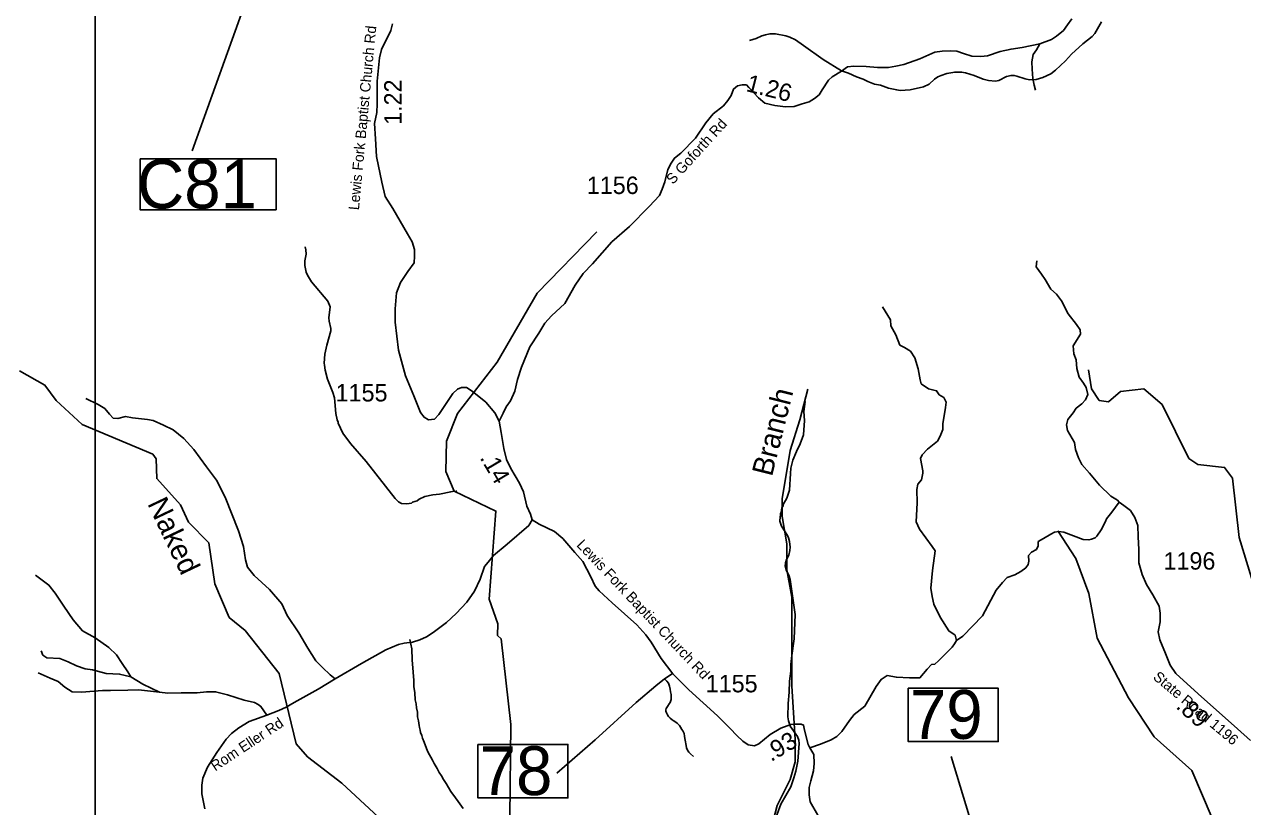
# Model space of a CAD drawing. Extents: x 1248089 to 1457196, y 820910 to 988753.
# Drawn here: x 1300259 to 1308985, y 877278 to 882884 of the extents above; entities that cross this region are included whole.
import ezdxf

# ---------------------------------------------------------------- set-up
doc = ezdxf.new("R2010")
doc.units = 0
for name, color, linetype in [('Exist Hydrographic Creek Single Shore', 7, 'Continuous'), ('Exist Hydrographic Misc Water Feature', 7, 'Continuous'), ('Exist Road Non-System Type 51', 7, 'Continuous'), ('Exist Road Secondary Structure Standard Bridge Number Label', 7, 'Continuous'), ('Exist Road Secondary Type 51 Attributed', 7, 'Continuous'), ('Exist Road Secondary Type 51 Label', 7, 'Continuous'), ('Map Preparation Inset Cut Line', 7, 'Continuous'), ('Prop GRAU CAT1 Cell', 7, 'Continuous'), ('Prop Guardrail Anchor Unit CELL', 7, 'Continuous'), ('Prop Lane Lines', 7, 'Continuous')]:
    doc.layers.add(name, color=color, linetype=linetype)

msp = doc.modelspace()

# ---------------------------------------------------------------- linework, layer by layer
at = {"layer": 'Exist Hydrographic Creek Single Shore'}
for points in [[(1304309.1, 876054.1), (1304084.2, 876058.7), (1303941.2, 875963), (1303891.1, 875980.4), (1303482.2, 876330.1), (1303255.2, 876594), (1302957.1, 877053), (1302532, 877445.5), (1302287.1, 877634.4), (1302205.1, 877727.9), (1302084.1, 878232.5), (1301841, 878539.5), (1301726.1, 878633.7), (1301624.1, 878875.4), (1301580, 879168.5), (1301434, 879315.8), (1301378, 879441.7), (1301207, 879628.9), (1301202, 879770.2), (1301178, 879803.5), (1300674, 880017.2), (1300487, 880188.3), (1300406, 880298.3), (1300225, 880400.4)], [(1304607.2, 875923.4), (1304830.5, 876199), (1305073.4, 876522.9), (1305142.8, 876580.8), (1305200.7, 876708), (1305362.6, 876835.2), (1305593.9, 877066.6), (1305651.8, 877286.4), (1305744.3, 877471.4), (1305779, 877598.7), (1305779, 877760.6), (1305755.9, 878142.3), (1305755.9, 878558.8), (1305755.9, 878778.5), (1305721.2, 878975.2), (1305721.2, 879160.2), (1305686.5, 879356.9), (1305686.5, 879484.1), (1305744.3, 879831.1), (1305813.7, 880050.9), (1305871.6, 880270.7)], [(1309746.2, 875554.1), (1309743.2, 875561), (1309715.2, 875778.2), (1309626.2, 875914.6), (1309588.3, 876046.7), (1309463.2, 876075.5), (1309365.2, 876136.5), (1309301.2, 876272.4), (1309271.3, 876414.1), (1309167.2, 876606.7), (1308835.2, 877033.5), (1308622.2, 877536.8), (1308352.2, 877778.6), (1308167.2, 878058), (1307943.2, 878486), (1307884.2, 878805.7), (1307790.2, 879057.1), (1307661.1, 879253.3)]]:
    msp.add_lwpolyline(points, dxfattribs=at)
at = {"layer": 'Exist Hydrographic Misc Water Feature'}
for points in [[(1305453.4, 882767.9), (1305501.7, 882782.5), (1305542.3, 882801.4), (1305566.5, 882808.6), (1305598.7, 882815.7), (1305638.8, 882816.5), (1305712.4, 882802.5), (1305742.2, 882791.6), (1305783.6, 882772.5), (1305839.8, 882731.8), (1305981.8, 882632.7), (1306111.5, 882551), (1306161.1, 882533.6), (1306218.3, 882507.9), (1306267.9, 882490.5), (1306301.4, 882473.5), (1306348.9, 882456.2), (1306390.7, 882446.9), (1306448.2, 882425.3), (1306507.8, 882413.6), (1306531.7, 882410.8), (1306603.9, 882414.8), (1306700.5, 882436), (1306739, 882454.9), (1306778.1, 882491.7), (1306802.6, 882507), (1306826.9, 882518.3), (1306867.3, 882531.1), (1306923.6, 882541.6), (1306971.7, 882542.2), (1306999.4, 882537.4), (1307063, 882517.5), (1307126.3, 882491.6), (1307166, 882482.5), (1307213.9, 882477.2), (1307238, 882480.5), (1307294.8, 882508.8), (1307327.1, 882517.9), (1307349.1, 882517.3), (1307368.9, 882512.7), (1307426.5, 882493), (1307458.2, 882486.1), (1307506.3, 882488.7), (1307554.7, 882503.3), (1307611.5, 882529.7), (1307644.2, 882554.7), (1307716.2, 882622.6), (1307759.6, 882669.3), (1307841.7, 882744.9), (1307907.2, 882797.1), (1307925.8, 882818.5), (1307974.2, 882901)], [(1304309.1, 876054.1), (1304307.2, 876297.2), (1304236.1, 876482.4), (1303767.1, 877109), (1303736.1, 877201.5), (1303743.1, 877867.7), (1303674.1, 878479.7), (1303649.1, 878503.2), (1303651.1, 878588.5), (1303589.1, 878763.8), (1303637.1, 879396.4), (1303337.6, 879538.2), (1303277.1, 879679.4), (1303282, 879895.9), (1303361.1, 880094.6), (1303645.1, 880463.1), (1303932, 880956.4), (1304359.1, 881397.5)], [(1302270.4, 881288.4), (1302275.9, 881268.3), (1302277, 881236.3), (1302267.7, 881188.5), (1302266.7, 881156.5), (1302277.4, 881108.3), (1302286.7, 881086), (1302315.4, 881039.3), (1302431.6, 880899.9), (1302448.4, 880859.4), (1302440.2, 880779.7), (1302441.5, 880755.7), (1302454.1, 880703.3), (1302453.6, 880687.4), (1302424.7, 880584.2), (1302410.9, 880520.6), (1302407.1, 880456.7), (1302408.6, 880440.7), (1302413.7, 880406.6), (1302429.9, 880342.2), (1302469.1, 880245), (1302480.1, 880206.7), (1302491, 880094.5), (1302499.7, 880050.2), (1302507.3, 880034), (1302507.1, 880026), (1302541, 879953.1), (1302594.9, 879879.5), (1302707.4, 879752.3), (1302914, 879486.4), (1302939.3, 879461.7), (1302959.1, 879451.1), (1302999, 879447.9), (1303031.2, 879453.1), (1303039.3, 879458.8), (1303071.7, 879469.9), (1303088, 879481.4), (1303128.5, 879500.2), (1303184.9, 879512.5), (1303233, 879517.2), (1303313.5, 879534.9), (1303337.6, 879538.2), (1303349.6, 879535.8), (1303357.7, 879541.6)], [(1309100.2, 878745.1), (1308961.1, 879207.5), (1308912.1, 879632), (1308856.2, 879708.6), (1308664.1, 879728.9), (1308599.1, 879772.9), (1308408.1, 880160.8), (1308277.2, 880271.8), (1308110.2, 880252.1), (1308025.2, 880178.3), (1307958.1, 880189.5), (1307902.2, 880272.7), (1307880.1, 880407.7)], [(1305850.7, 880181.3), (1305842.7, 880109.5), (1305846.9, 880045.5), (1305840.1, 879941.7), (1305816.3, 879878.4), (1305788.7, 879823.2), (1305762.9, 879759.9), (1305749.3, 879704.4), (1305745.8, 879664.4), (1305738.9, 879544.7), (1305719.3, 879489.4), (1305694, 879442.1), (1305693.7, 879434.1), (1305685.3, 879418.3), (1305680.3, 879386.4), (1305676.1, 879378.6), (1305675.7, 879362.6), (1305671.5, 879354.8), (1305670.6, 879322.8), (1305681.6, 879288.5), (1305725.8, 879221.3), (1305733.2, 879205), (1305740.5, 879176.8), (1305745.3, 879136.7), (1305742.7, 879112.8), (1305733.8, 879081), (1305716.9, 879049.5), (1305710.3, 879025.7), (1305709.6, 879001.8), (1305716.7, 878971.6), (1305735.8, 878937.1), (1305744.8, 878904.8), (1305779.9, 878655.8), (1305772.9, 878480.1), (1305755.6, 878360.7), (1305749.8, 878296.8), (1305748.4, 878248.9), (1305740.4, 878177.1), (1305738.2, 878097.3), (1305729.9, 878017.5), (1305727.2, 877921.6), (1305732.4, 877893.4), (1305745.3, 877855.1), (1305797.2, 877779.6), (1305806.6, 877755.3), (1305807.9, 877731.4), (1305798.4, 877603.6), (1305784.3, 877532), (1305771, 877484.5), (1305749.1, 877421.1), (1305677.6, 877295.2), (1305625.6, 877152.8)]]:
    msp.add_lwpolyline(points, dxfattribs=at)
at = {"layer": 'Exist Road Non-System Type 51'}
msp.add_line((1304898.5, 878229.8), (1304843.5, 878193.1), dxfattribs=at)
for points in [[(1307531.8, 882743.2), (1307507.8, 882701.1), (1307486, 882667.1), (1307476.3, 882616.1), (1307478.7, 882562.7), (1307483.5, 882494.7), (1307493.2, 882448.5), (1307500.5, 882412.1)], [(1307732.2, 880053.2), (1307770.8, 880099.6), (1307793.4, 880132.8), (1307833.5, 880164.2), (1307859.7, 880193.8), (1307875.3, 880232.2), (1307864.8, 880280.3), (1307845.7, 880313.5), (1307814.3, 880355.3), (1307796.9, 880418.1), (1307793.4, 880480.9), (1307776, 880522.8), (1307770.7, 880580.3), (1307824.8, 880664), (1307821.2, 880694.1), (1307795, 880732.4), (1307735.8, 880809.2), (1307688.7, 880903.4), (1307652.1, 880950.5), (1307610.3, 880987.1), (1307571.9, 881055.1), (1307544.1, 881093.5), (1307505.7, 881145.8), (1307510.9, 881189.4)], [(1306936.9, 878468.2), (1306925.2, 878506.1), (1306882, 878537.5), (1306819.3, 878635.6), (1306772.2, 878729.8), (1306760.5, 878784.7), (1306752.6, 878843.6), (1306764.4, 878969.2), (1306784, 879110.5), (1306760.5, 879141.9), (1306670.3, 879267.4), (1306646.7, 879318.5), (1306654.6, 879455.8), (1306650.7, 879550), (1306658.5, 879589.2), (1306685.9, 879620.6), (1306693.8, 879667.7), (1306693.8, 879683.4), (1306678.1, 879773.7), (1306689.8, 879799.4), (1306729, 879838.6), (1306799.6, 879897.5), (1306819.2, 879932.8), (1306838.8, 879979.9), (1306838.8, 880023.1), (1306846.6, 880078), (1306855.8, 880138.2), (1306861, 880177.5), (1306845.3, 880208.8), (1306811.3, 880229.8), (1306793, 880258.6), (1306735.5, 880271.6), (1306683.2, 880308.3), (1306675.4, 880337), (1306662.3, 880415.5), (1306636.2, 880494), (1306607.4, 880541.1), (1306563, 880567.3), (1306529, 880585.6), (1306500.2, 880658.9), (1306466.2, 880724.3), (1306463.6, 880766.1), (1306406.1, 880860.3)], [(1300698.6, 880202.1), (1300788.4, 880160.8), (1300834.6, 880131.7), (1300868.5, 880090.4), (1300895.2, 880061.2), (1300929.2, 880058.8), (1300982.6, 880073.4), (1301033.6, 880063.7), (1301140.4, 880051.5), (1301181.6, 880044.2), (1301254.4, 880012.7), (1301324.8, 879978.6), (1301400.1, 879915.5), (1301472.9, 879837.8), (1301562.7, 879713.9), (1301635.5, 879616.8), (1301696.1, 879495.3), (1301793.2, 879254.9), (1301829.6, 879143.1), (1301843.5, 879045.7), (1301858, 878994.7), (1301904.1, 878933.9), (1302015.8, 878834.4), (1302103.2, 878732.4), (1302142, 878647.3), (1302224.5, 878523.5), (1302290, 878414.2), (1302345.9, 878321.9), (1302394.4, 878275.7), (1302450.2, 878222.3), (1302484.2, 878193.2)], [(1308100.2, 879460), (1308047.9, 879388.5), (1308011.3, 879341.4), (1308002.6, 879320.4), (1307973, 879261.1), (1307939.9, 879215.8), (1307929.4, 879205.3), (1307903.3, 879194.8), (1307884.1, 879189.6), (1307844, 879191.4), (1307774.3, 879217.5), (1307704.6, 879245.4), (1307668, 879248.9), (1307636.6, 879243.7), (1307612.2, 879231.5), (1307558.2, 879200.1), (1307521.6, 879177.4), (1307519.8, 879147.8), (1307509.4, 879121.6), (1307472.8, 879102.4), (1307451.8, 879078), (1307453.6, 879036.1), (1307448.4, 879013.4), (1307432.7, 878989)], [(1300339.7, 878936.4), (1300434.4, 878866), (1300480.5, 878807.7), (1300541.2, 878715.4), (1300609.1, 878615.8), (1300674.7, 878538.1), (1300766.9, 878487.1), (1300864, 878419.1), (1300919.8, 878365.6), (1300958.6, 878304.9), (1300999.9, 878244.2), (1301021.7, 878207.8), (1301106.7, 878156.8), (1301228, 878098.5), (1301286.3, 878091.2), (1301380.9, 878093.6), (1301497.4, 878093.6), (1301563, 878100.9), (1301628.5, 878100.9), (1301713.4, 878079.1), (1301832.4, 878040.2), (1301907.6, 878023.2), (1301934.3, 878011), (1301953.7, 877996.5), (1301995.1, 877933.8)], [(1305884.7, 877700.5), (1305960.4, 877726.5), (1306038.8, 877757.9), (1306078, 877781.4), (1306113.3, 877816.7), (1306168.2, 877895.2), (1306203.5, 877938.4), (1306278, 877997.3), (1306360.4, 878138.5), (1306395.7, 878189.6), (1306438.8, 878217), (1306505.5, 878205.3), (1306599.6, 878201.3), (1306674.1, 878201.3), (1306725.1, 878264.1), (1306756.5, 878295.5), (1306780, 878299.4), (1306807.5, 878323), (1306905.5, 878421.1), (1306921.2, 878444.6), (1306936.9, 878468.2), (1306980, 878499.6), (1307121.2, 878644.8), (1307219.2, 878829.2), (1307266.3, 878884.2), (1307297.7, 878919.5), (1307352.6, 878939.1), (1307395.7, 878962.7), (1307432.7, 878989)], [(1303020.8, 878475.8), (1303033.3, 878409.3), (1303037.5, 878329.2), (1303043.6, 878241), (1303048.2, 878182.9), (1303049.1, 878138.9), (1303056, 878092.7), (1303058.8, 878042.6), (1303064.2, 878014.5), (1303067.7, 877986.4), (1303074.9, 877956.2), (1303076, 877922.2), (1303081.4, 877891.9), (1303086.5, 877859.7), (1303088.3, 877845.7), (1303093.9, 877825.6), (1303097.5, 877809.5), (1303104.9, 877787.3), (1303110.5, 877769.2), (1303122, 877739), (1303131.2, 877712.7), (1303144.6, 877682.3), (1303152.1, 877666.1), (1303161.8, 877649.9), (1303169.5, 877633.7), (1303183, 877611.4), (1303194.4, 877587.2), (1303215.6, 877550.6), (1303230.9, 877522.2), (1303246.4, 877499.9), (1303261.7, 877471.4), (1303281.2, 877445), (1303313.8, 877386.3), (1303346.7, 877341.4), (1303366.2, 877315), (1303401, 877264.1)], [(1301021.7, 878207.8), (1300941.5, 878228.2), (1300844.4, 878233.1), (1300747.4, 878257.4), (1300694, 878264.7), (1300633.3, 878286.5), (1300572.6, 878315.7), (1300511.9, 878340), (1300419.7, 878344.8), (1300390.6, 878364.2), (1300378.5, 878393.4)], [(1301228, 878098.5), (1301077.4, 878114.1), (1300999.8, 878111.6), (1300876, 878109.2), (1300817.7, 878109.2), (1300667.3, 878099.5), (1300601.7, 878101.9), (1300548.3, 878133.5), (1300499.8, 878174.8), (1300444, 878199.1), (1300356.6, 878237.9)], [(1304073.4, 877517), (1304347.9, 877756.4), (1304642, 878023.3), (1304783.2, 878144.9), (1304843.5, 878193.1)], [(1304843.5, 878193.1), (1304861.2, 878176.7), (1304872.9, 878162.5), (1304880.5, 878140.3), (1304883.9, 878120.2), (1304887.5, 878100.1), (1304891.1, 878081.9), (1304892.6, 878067.8), (1304892.2, 878045.8), (1304883.8, 878024.2), (1304877.6, 878014.3), (1304865, 877996.5), (1304856.7, 877980.7), (1304854.5, 877972.7), (1304854.3, 877962.7), (1304858.1, 877950.6), (1304865.6, 877936.5), (1304873.4, 877924.3), (1304885.1, 877911.9), (1304898.9, 877899.6), (1304906.8, 877895.4), (1304918.7, 877889.2), (1304934.2, 877876.9), (1304946, 877864.4), (1304951.9, 877858.3), (1304959.7, 877848.1), (1304969.4, 877831.9), (1304975.2, 877821.8), (1304984.6, 877801.6), (1304988.2, 877783.5), (1304989.8, 877765.5), (1304995.2, 877741.4), (1304996.9, 877727.3), (1304998.7, 877717.3), (1305002.3, 877699.2), (1305007.8, 877682.9), (1305017.5, 877668.7), (1305029.3, 877656.4), (1305050.9, 877638)]]:
    msp.add_lwpolyline(points, dxfattribs=at)
at = {"layer": 'Exist Road Secondary Structure Standard Bridge Number Label'}
msp.add_line((1307919.3, 874272), (1306898.1, 877637.1), dxfattribs=at)
for points in [[(1306590.1, 878126.4), (1307234.2, 878126.4), (1307234.2, 877744.1), (1306590.1, 877744.1)], [(1303508, 877723.4), (1304152.2, 877723.4), (1304152.2, 877341.1), (1303508, 877341.1)]]:
    msp.add_lwpolyline(points, close=True, dxfattribs=at)
at = {"layer": 'Exist Road Secondary Type 51 Attributed'}
for points in [[(1302896, 882887.6), (1302882.8, 882839.6), (1302816.7, 882702.3), (1302803.4, 882644.4), (1302785.3, 882477.4), (1302787.1, 882404.1), (1302787.1, 882313.2), (1302783.8, 882251.9), (1302767.2, 882174.2), (1302773.8, 882063.4), (1302782.1, 881936), (1302818.3, 881753.3), (1302843.1, 881650.8), (1302897.7, 881563.1), (1303003.5, 881382.8), (1303036.3, 881324.2), (1303052.9, 881269.6), (1303054.5, 881221.6), (1303051.2, 881175.3), (1303006.6, 881112.4), (1302952, 881033), (1302925.6, 880960.2), (1302915.7, 880844.4), (1302914.2, 880749.5), (1302939, 880549.3), (1302988.5, 880364.1), (1303047.9, 880220.9), (1303097.5, 880101.8), (1303122.3, 880068.7), (1303153.7, 880048.8), (1303196.6, 880055.4), (1303228, 880086.9), (1303328.9, 880237.4), (1303361.9, 880270.5), (1303390, 880282.1), (1303424.7, 880280.4), (1303466.1, 880255.6), (1303565.2, 880176.2), (1303629.7, 880100.1), (1303659.5, 880039.8)], [(1307763, 882923.1), (1307730.9, 882880.3), (1307703.1, 882839.6), (1307651.7, 882798.9), (1307615.3, 882775.3), (1307531.8, 882743.2), (1307405.5, 882717.5), (1307326.3, 882706.7), (1307249.3, 882689.6), (1307157.2, 882657.5), (1307110.1, 882653.2), (1307045.9, 882655.3), (1306985.9, 882674.6), (1306938.8, 882691.8), (1306891.8, 882693.9), (1306834, 882691.8), (1306780.4, 882683.2), (1306673.4, 882636), (1306559.3, 882595.5), (1306501.5, 882584.8), (1306448, 882574.1), (1306370.9, 882574.1), (1306289.6, 882582.7), (1306199.7, 882584.8), (1306154.7, 882578.4), (1306111.9, 882548.4), (1306045.5, 882507.7), (1306017.7, 882484.1), (1305972.7, 882413.4), (1305953.2, 882379.7), (1305917.9, 882352.9), (1305879.3, 882329.3), (1305831.2, 882313.3), (1305773.4, 882295.1), (1305710.2, 882292.9), (1305635.3, 882301.5), (1305563.6, 882319.7), (1305517.5, 882356.1), (1305449, 882431.1), (1305430.4, 882449.3), (1305401.5, 882449.3), (1305366.2, 882442.9), (1305337.3, 882419.3), (1305322.3, 882374.3), (1305298.8, 882337.9), (1305266.7, 882299.3), (1305192.8, 882242.6), (1305139.5, 882178.6), (1305066.7, 882068.3), (1304960, 881960.7), (1304916.1, 881925.4), (1304892.6, 881887.9), (1304868, 881842.9), (1304845.5, 881755), (1304828.4, 881702.6), (1304808, 881656.5), (1304735.2, 881579.4), (1304593.1, 881435.5), (1304466.8, 881325.2), (1304327.6, 881167.7), (1304260.6, 881097.8), (1304203.8, 881014.2), (1304130, 880883.5), (1304035.8, 880795.7), (1303985.8, 880742.7), (1303943, 880669.9), (1303879.8, 880572.4), (1303821, 880427.8), (1303791.1, 880338.6), (1303771.8, 880255), (1303740.8, 880186.4), (1303710.8, 880143.6), (1303688.3, 880096.5), (1303659.5, 880039.8)], [(1303659.5, 880039.8), (1303673, 879959), (1303692.5, 879843.6), (1303712.1, 879765.4), (1303743.3, 879700.9), (1303805.8, 879595.4), (1303833.1, 879532.8), (1303858.5, 879431.2), (1303883.6, 879373.3), (1303895.4, 879332.3)], [(1309042.3, 877750.9), (1308948.4, 877836.3), (1308666.8, 878086.1), (1308507.3, 878232.5), (1308466.7, 878292.3), (1308432.6, 878375.5), (1308392.1, 878473.8), (1308381.4, 878531.4), (1308394.2, 878601.9), (1308394.2, 878663.8), (1308387.8, 878715), (1308340.9, 878796.2), (1308296, 878868.8), (1308266.4, 878942.4), (1308242.9, 879025.7), (1308240.8, 879119.7), (1308236.5, 879211.5), (1308234.4, 879292.6), (1308213.1, 879350.3), (1308183.2, 879399.4), (1308134.1, 879435.7), (1308100.2, 879460), (1308089.3, 879474.1), (1308040.6, 879502.9), (1307959.5, 879581.9), (1307889.1, 879667.3), (1307833.6, 879729.2), (1307810.2, 879778.3), (1307787.7, 879837.6), (1307781.3, 879886.7), (1307730.1, 879974.2), (1307723.7, 880014.8), (1307732.2, 880053.2)], [(1303895.4, 879332.3), (1303872.5, 879293), (1303716.4, 879157.7), (1303620.2, 879077), (1303581.2, 879030.1), (1303555.2, 878998.9), (1303523.9, 878907.8), (1303482.3, 878821.9), (1303427.7, 878743.8), (1303352.3, 878663.1), (1303282, 878598), (1303188, 878525.2), (1303139.9, 878495.3), (1303091.8, 878474.5), (1303038.4, 878457.5), (1302979.9, 878449.7), (1302938.3, 878440.6), (1302848.6, 878401.6), (1302674.3, 878303.9), (1302484.2, 878193.2), (1302364, 878119.6), (1302191, 878023.3), (1302133, 877991.1), (1302081, 877967.7), (1301995.1, 877933.8), (1301870.3, 877887), (1301794.9, 877842.7), (1301742.8, 877801.1), (1301704.4, 877761.5), (1301638.1, 877665.2), (1301571.7, 877561), (1301536.6, 877481.6), (1301530.1, 877432.2), (1301530.1, 877369.7), (1301550.9, 877261.7)], [(1303895.4, 879332.3), (1303946.9, 879302.5), (1304055.4, 879249.5), (1304115.1, 879199.3), (1304201.9, 879100.2), (1304260.2, 879035), (1304315.8, 878925.1), (1304348.1, 878857.7), (1304375.2, 878823.7), (1304470.2, 878738.2), (1304646.1, 878580), (1304711.2, 878508), (1304749.2, 878457.8), (1304821.1, 878339.7), (1304903.6, 878230.5), (1305018.9, 878115.1), (1305223.7, 877927.8), (1305315.5, 877837.5), (1305362.9, 877787.2), (1305406.3, 877746.5), (1305444.3, 877722.1), (1305487.7, 877713.9), (1305520.3, 877728.9), (1305600.3, 877795.4), (1305677.6, 877841.5), (1305748.1, 877866), (1305780.7, 877870), (1305822.7, 877870), (1305839.9, 877862), (1305848.1, 877825.3), (1305872.5, 877723.5), (1305884.7, 877700.5), (1305913.1, 877652.1), (1305917.1, 877587), (1305911.7, 877535.4), (1305891.4, 877463.4), (1305879.2, 877415.9), (1305880.5, 877363), (1305888.7, 877312.7), (1305942.9, 877217.7)]]:
    msp.add_lwpolyline(points, dxfattribs=at)
at = {"layer": 'Map Preparation Inset Cut Line'}
msp.add_lwpolyline([(1313026.2, 867658.5), (1300766.9, 867658.5), (1300766.9, 889680.3), (1313026.2, 889680.3)], close=True, dxfattribs=at)
at = {"layer": 'Prop Guardrail Anchor Unit CELL'}
msp.add_line((1302248.3, 884168.2), (1301461.1, 881977.6), dxfattribs=at)
msp.add_lwpolyline([(1301088.3, 881921.2), (1302062, 881921.2), (1302062, 881554.9), (1301088.3, 881554.9)], close=True, dxfattribs=at)

# ---------------------------------------------------------------- texts
at = {"layer": 'Exist Hydrographic Creek Single Shore'}
for s, rotation, p in [('Branch', 75.96376, (1305613.9, 879638)), ('Naked', 295.4892, (1301137.2, 879449.9))]:
    msp.add_text(s, height=150, rotation=rotation, dxfattribs=at).set_placement(p)
at = {"layer": 'Exist Road Secondary Structure Standard Bridge Number Label'}
for s, p in [('79', (1306602.6, 877763.8)), ('78', (1303520.6, 877360.9))]:
    msp.add_text(s, height=350, dxfattribs=at).set_placement(p)
at = {"layer": 'Exist Road Secondary Type 51 Label'}
for s, rotation, p in [('Lewis Fork Baptist Church Rd', 84.59553, (1302655.3, 881549.9)), ('S Goforth Rd', 47.80519, (1304904.6, 881732.3)), ('Lewis Fork Baptist Church Rd', 313.34881, (1304209.5, 879149.1)), ('State Road 1196', 320.01502, (1308338, 878197.3)), ('Rom Eller Rd', 33.52252, (1301625.7, 877529.4))]:
    msp.add_text(s, height=75, rotation=rotation, dxfattribs=at).set_placement(p)
at = {"layer": 'Prop GRAU CAT1 Cell'}
for s, rotation, p in [('1.26', 345.7521, (1305422.3, 882406.3)), ('1.22', 90, (1302961.3, 882163.4)), ('.14', 300.63064, (1303518.1, 879777.7)), ('.89', 318.42474, (1308501, 877988.6)), ('.93', 30.83594, (1305607.6, 877596.8))]:
    msp.add_text(s, height=125, rotation=rotation, dxfattribs=at).set_placement(p)
at = {"layer": 'Prop Guardrail Anchor Unit CELL'}
msp.add_text('C81', height=350, dxfattribs=at).set_placement((1301066.1, 881564.6))
at = {"layer": 'Prop Lane Lines'}
for s, p in [('1156', (1304287.4, 881667.9)), ('1155', (1302488.3, 880181.5)), ('1196', (1308418.2, 878976.5)), ('1155', (1305139.2, 878097.1))]:
    msp.add_text(s, height=125, dxfattribs=at).set_placement(p)

doc.saveas('drawing.dxf')
